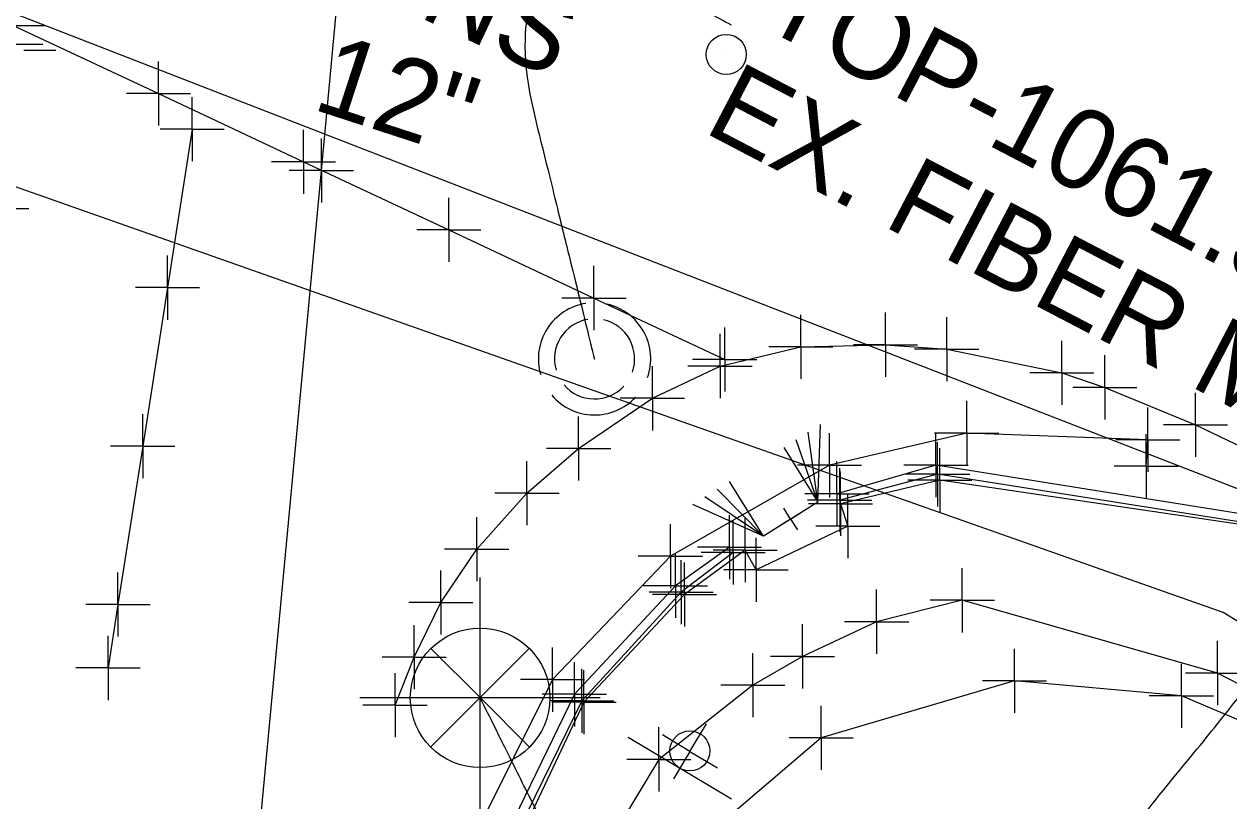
# Model space of a CAD drawing. Extents: x 0 to 1944463, y 0 to 420651.
# Drawn here: x 1942710.7 to 1942785.8, y 417761.8 to 417810.2 of the extents above; entities that cross this region are included whole.
import ezdxf

# ---------------------------------------------------------------- set-up
doc = ezdxf.new("R2010")
doc.units = 0
for name, color, linetype in [('AERIAL - CTRL - Points', 7, 'Continuous'), ('AERIAL - CTRL - Text', 7, 'Continuous'), ('SUR - DRG - Storm Sewer', 7, 'Continuous'), ('SUR - DRG - Storm Sewer Text', 7, 'Continuous'), ('SUR - DTM - Breaklines', 7, 'Continuous'), ('SUR - DTM - Breaklines - Points - Locators', 7, 'Continuous'), ('SUR - DTM - Spot Points - Locators', 7, 'Continuous'), ('SUR - PROPERTY - Property Lines', 7, 'Continuous'), ('SUR - TR-CTRL - Pavement Marking', 7, 'Continuous'), ('SUR - TR-CTRL - Pavement Marking - Points - Locators', 7, 'Continuous'), ('SUR - TR-CTRL - Signs and Devices', 7, 'Continuous'), ('SUR - TR-CTRL - Signs and Devices - Points - Locators', 7, 'Continuous'), ('SUR - TRAN - Features', 7, 'Continuous'), ('SUR - TRAN - Features - Points - Locators', 7, 'Continuous'), ('SUR - TRAN - Roads', 7, 'Continuous'), ('SUR - UTL - Fiber Optic Cable (Underground)', 7, 'Continuous'), ('SUR - UTL - Fiber Optic Cable (Underground) Text', 7, 'Continuous'), ('SUR - UTL - Water', 7, 'Continuous'), ('SUR - UTL - Water - Points - Locators', 7, 'Continuous')]:
    doc.layers.add(name, color=color, linetype=linetype)

msp = doc.modelspace()

# ---------------------------------------------------------------- linework, layer by layer
at = {"layer": 'AERIAL - CTRL - Points'}
for p, q in [((1942739.116, 417768.228), (1942739.116, 417775.728)), ((1942739.116, 417768.228), (1942736.047, 417771.297)), ((1942739.116, 417768.228), (1942742.184, 417771.297)), ((1942731.616, 417768.228), (1942739.116, 417768.228)), ((1942736.032, 417765.145), (1942739.116, 417768.228)), ((1942739.116, 417768.228), (1942739.116, 417768.228)), ((1942739.116, 417768.228), (1942746.615, 417768.228)), ((1942742.199, 417765.145), (1942739.116, 417768.228)), ((1942739.116, 417760.729), (1942739.116, 417768.228))]:
    msp.add_line(p, q, dxfattribs=at)
msp.add_circle((1942739.116, 417768.213), 4.35, dxfattribs=at)
at = {"layer": 'AERIAL - CTRL - Text'}
msp.add_open_spline([(1942778.809, 417721.49), (1942758.242, 417729.869), (1942739.116, 417768.228), (1942739.116, 417768.228)], degree=2, dxfattribs=at)
at = {"layer": 'SUR - DRG - Storm Sewer'}
msp.add_lwpolyline([(1942686.1, 417820.21), (1942792.82, 417778.75)], dxfattribs=at)
at = {"layer": 'SUR - DRG - Storm Sewer Text'}
msp.add_open_spline([(1942822.792, 417707.352), (1942764.259, 417740.655), (1942794.051, 417777.755), (1942794.051, 417777.755)], degree=2, dxfattribs=at)
at = {"layer": 'SUR - DTM - Breaklines'}
for points in [[(1942791.46, 417777.632), (1942789.584, 417778.697), (1942767.646, 417782.153), (1942761.543, 417780.542)], [(1942754.9, 417777.285), (1942751.657, 417774.809), (1942745.466, 417768.026), (1942741.083, 417759.074), (1942738.467, 417741.187), (1942737.586, 417732.685)], [(1942921.107, 417679.837), (1942919.961, 417678.775), (1942913.528, 417683.522), (1942876.22, 417712.505), (1942837.487, 417736.737), (1942800.473, 417757.298), (1942794.469, 417761.004), (1942792.318, 417764.328), (1942782.845, 417768.341), (1942772.445, 417769.28), (1942760.386, 417765.72), (1942751.56, 417758.18), (1942747.81, 417744.492), (1942745.106, 417731.919)]]:
    msp.add_lwpolyline(points, dxfattribs=at)
at = {"layer": 'SUR - DTM - Breaklines - Points - Locators'}
for p, q in [((1942767.646, 417782.153), (1942767.646, 417784.153)), ((1942761.543, 417780.542), (1942761.543, 417782.542)), ((1942767.646, 417782.153), (1942765.646, 417782.153)), ((1942767.646, 417782.153), (1942769.646, 417782.153)), ((1942767.646, 417782.153), (1942767.646, 417780.153)), ((1942761.543, 417780.542), (1942759.543, 417780.542)), ((1942761.543, 417780.542), (1942763.543, 417780.542)), ((1942761.543, 417780.542), (1942761.543, 417778.542)), ((1942754.9, 417777.285), (1942754.9, 417779.285)), ((1942754.9, 417777.285), (1942752.9, 417777.285)), ((1942754.9, 417777.285), (1942756.9, 417777.285)), ((1942754.9, 417777.285), (1942754.9, 417775.285)), ((1942751.657, 417774.809), (1942751.657, 417776.809)), ((1942751.657, 417774.809), (1942749.657, 417774.809)), ((1942751.657, 417774.809), (1942753.657, 417774.809)), ((1942751.657, 417774.809), (1942751.657, 417772.809)), ((1942772.445, 417769.28), (1942772.445, 417771.28)), ((1942745.466, 417768.026), (1942745.466, 417770.026)), ((1942782.845, 417768.341), (1942782.845, 417770.341)), ((1942772.445, 417769.28), (1942770.445, 417769.28)), ((1942772.445, 417769.28), (1942774.445, 417769.28)), ((1942772.445, 417769.28), (1942772.445, 417767.28)), ((1942782.845, 417768.341), (1942780.845, 417768.341)), ((1942782.845, 417768.341), (1942784.845, 417768.341)), ((1942782.845, 417768.341), (1942782.845, 417766.341)), ((1942745.466, 417768.026), (1942743.466, 417768.026)), ((1942745.466, 417768.026), (1942747.466, 417768.026)), ((1942745.466, 417768.026), (1942745.466, 417766.026)), ((1942760.386, 417765.72), (1942760.386, 417767.72)), ((1942760.386, 417765.72), (1942758.386, 417765.72)), ((1942760.386, 417765.72), (1942762.386, 417765.72)), ((1942760.386, 417765.72), (1942760.386, 417763.72))]:
    msp.add_line(p, q, dxfattribs=at)
at = {"layer": 'SUR - DTM - Spot Points - Locators'}
msp.add_line((1942754.48, 417808.32), (1942754.48, 417808.32), dxfattribs=at)
msp.add_circle((1942754.469, 417808.331), 1.25, dxfattribs=at)
at = {"layer": 'SUR - PROPERTY - Property Lines'}
for p, q in [((1942759.122, 417790.098), (1942759.122, 417792.098)), ((1942764.401, 417790.234), (1942764.401, 417792.234)), ((1942768.216, 417789.961), (1942768.216, 417791.961)), ((1942754.081, 417788.905), (1942754.081, 417790.905)), ((1942759.122, 417790.098), (1942757.122, 417790.098)), ((1942759.122, 417790.098), (1942761.122, 417790.098)), ((1942759.122, 417790.098), (1942759.122, 417788.098)), ((1942764.401, 417790.234), (1942762.401, 417790.234)), ((1942764.401, 417790.234), (1942766.401, 417790.234)), ((1942764.401, 417790.234), (1942764.401, 417788.234)), ((1942768.216, 417789.961), (1942766.216, 417789.961)), ((1942768.216, 417789.961), (1942770.216, 417789.961)), ((1942768.216, 417789.961), (1942768.216, 417787.961)), ((1942749.858, 417786.894), (1942749.858, 417788.894)), ((1942754.081, 417788.905), (1942752.081, 417788.905)), ((1942754.081, 417788.905), (1942756.081, 417788.905)), ((1942754.081, 417788.905), (1942754.081, 417786.905)), ((1942749.858, 417786.894), (1942747.858, 417786.894)), ((1942749.858, 417786.894), (1942751.858, 417786.894)), ((1942749.858, 417786.894), (1942749.858, 417784.894)), ((1942769.462, 417784.726), (1942769.462, 417786.726)), ((1942780.758, 417784.311), (1942780.758, 417786.311)), ((1942745.26, 417783.759), (1942745.26, 417785.759)), ((1942760.904, 417782.715), (1942760.904, 417784.715)), ((1942769.462, 417784.726), (1942767.462, 417784.726)), ((1942769.462, 417784.726), (1942771.462, 417784.726)), ((1942769.462, 417784.726), (1942769.462, 417782.726)), ((1942780.758, 417784.311), (1942778.758, 417784.311)), ((1942780.651, 417782.667), (1942780.651, 417784.667)), ((1942780.758, 417784.311), (1942782.758, 417784.311)), ((1942780.758, 417784.311), (1942780.758, 417782.311)), ((1942745.26, 417783.759), (1942743.26, 417783.759)), ((1942745.26, 417783.759), (1942747.26, 417783.759)), ((1942745.26, 417783.759), (1942745.26, 417781.759)), ((1942742.041, 417780.981), (1942742.041, 417782.981)), ((1942760.904, 417782.715), (1942758.904, 417782.715)), ((1942760.904, 417782.715), (1942762.904, 417782.715)), ((1942760.904, 417782.715), (1942760.904, 417780.715)), ((1942780.651, 417782.667), (1942778.651, 417782.667)), ((1942780.651, 417782.667), (1942782.651, 417782.667)), ((1942780.651, 417782.667), (1942780.651, 417780.667)), ((1942742.041, 417780.981), (1942740.041, 417780.981)), ((1942742.041, 417780.981), (1942744.041, 417780.981)), ((1942742.041, 417780.981), (1942742.041, 417778.981)), ((1942738.908, 417777.491), (1942738.908, 417779.491)), ((1942750.983, 417777.043), (1942750.983, 417779.043)), ((1942738.908, 417777.491), (1942736.908, 417777.491)), ((1942738.908, 417777.491), (1942740.908, 417777.491)), ((1942738.908, 417777.491), (1942738.908, 417775.491)), ((1942750.983, 417777.043), (1942748.983, 417777.043)), ((1942750.983, 417777.043), (1942752.983, 417777.043)), ((1942750.983, 417777.043), (1942750.983, 417775.043)), ((1942736.673, 417774.165), (1942736.673, 417776.165)), ((1942736.673, 417774.165), (1942734.673, 417774.165)), ((1942736.673, 417774.165), (1942738.673, 417774.165)), ((1942736.673, 417774.165), (1942736.673, 417772.165)), ((1942735.011, 417770.757), (1942735.011, 417772.757)), ((1942743.631, 417769.353), (1942743.631, 417771.353)), ((1942735.011, 417770.757), (1942733.011, 417770.757)), ((1942735.011, 417770.757), (1942737.011, 417770.757)), ((1942735.011, 417770.757), (1942735.011, 417768.757)), ((1942733.812, 417767.758), (1942733.812, 417769.758)), ((1942743.631, 417769.353), (1942741.631, 417769.353)), ((1942743.631, 417769.353), (1942745.631, 417769.353)), ((1942743.631, 417769.353), (1942743.631, 417767.353)), ((1942733.812, 417767.758), (1942731.812, 417767.758)), ((1942733.812, 417767.758), (1942735.812, 417767.758)), ((1942733.812, 417767.758), (1942733.812, 417765.758))]:
    msp.add_line(p, q, dxfattribs=at)
at = {"layer": 'SUR - TR-CTRL - Pavement Marking'}
for points in [[(1942710.007, 417810.141), (1942719.059, 417805.892), (1942728.111, 417801.642), (1942737.164, 417797.393), (1942746.216, 417793.144), (1942754.37, 417789.316)], [(1942721.166, 417803.674), (1942719.623, 417793.794), (1942718.079, 417783.914), (1942716.535, 417774.034), (1942715.917, 417770.08)], [(1942775.389, 417788.48), (1942778.077, 417787.573), (1942783.724, 417785.239), (1942789.24, 417782.599), (1942795.258, 417779.283), (1942803.951, 417774.34), (1942812.644, 417769.396), (1942821.336, 417764.453), (1942822.904, 417763.561), (1942831.499, 417758.45), (1942840.094, 417753.338), (1942848.689, 417748.226), (1942855.367, 417744.255), (1942863.768, 417738.83), (1942872.168, 417733.405), (1942877.884, 417729.714), (1942886.158, 417724.097), (1942893.929, 417718.822)]]:
    msp.add_lwpolyline(points, dxfattribs=at)
at = {"layer": 'SUR - TR-CTRL - Pavement Marking - Points - Locators'}
for p, q in [((1942710.007, 417810.141), (1942712.007, 417810.141)), ((1942709.862, 417808.967), (1942711.862, 417808.967)), ((1942710.665, 417808.592), (1942712.665, 417808.592)), ((1942719.059, 417805.892), (1942719.059, 417807.892)), ((1942719.059, 417805.892), (1942717.059, 417805.892)), ((1942719.059, 417805.892), (1942721.059, 417805.892)), ((1942719.059, 417805.892), (1942719.059, 417803.892)), ((1942721.166, 417803.674), (1942721.166, 417805.674)), ((1942721.166, 417803.674), (1942719.166, 417803.674)), ((1942721.166, 417803.674), (1942723.166, 417803.674)), ((1942721.166, 417803.674), (1942721.166, 417801.674)), ((1942728.111, 417801.642), (1942728.111, 417803.642)), ((1942728.111, 417801.642), (1942726.111, 417801.642)), ((1942728.111, 417801.642), (1942730.111, 417801.642)), ((1942728.111, 417801.642), (1942728.111, 417799.642)), ((1942737.164, 417797.393), (1942737.164, 417799.393)), ((1942708.971, 417798.737), (1942710.971, 417798.737)), ((1942737.164, 417797.393), (1942735.164, 417797.393)), ((1942737.164, 417797.393), (1942739.164, 417797.393)), ((1942737.164, 417797.393), (1942737.164, 417795.393)), ((1942719.623, 417793.794), (1942719.623, 417795.794)), ((1942746.216, 417793.144), (1942746.216, 417795.144)), ((1942719.623, 417793.794), (1942717.623, 417793.794)), ((1942719.623, 417793.794), (1942721.623, 417793.794)), ((1942719.623, 417793.794), (1942719.623, 417791.794)), ((1942746.216, 417793.144), (1942744.216, 417793.144)), ((1942746.216, 417793.144), (1942748.216, 417793.144)), ((1942746.216, 417793.144), (1942746.216, 417791.144)), ((1942754.37, 417789.316), (1942754.37, 417791.316)), ((1942775.389, 417788.48), (1942775.389, 417790.48)), ((1942775.389, 417788.48), (1942775.389, 417790.48)), ((1942754.37, 417789.316), (1942752.37, 417789.316)), ((1942754.37, 417789.316), (1942756.37, 417789.316)), ((1942754.37, 417789.316), (1942754.37, 417787.316)), ((1942778.077, 417787.573), (1942778.077, 417789.573)), ((1942775.389, 417788.48), (1942773.389, 417788.48)), ((1942775.389, 417788.48), (1942773.389, 417788.48)), ((1942775.389, 417788.48), (1942777.389, 417788.48)), ((1942775.389, 417788.48), (1942775.389, 417786.48)), ((1942775.389, 417788.48), (1942777.389, 417788.48)), ((1942775.389, 417788.48), (1942775.389, 417786.48)), ((1942778.077, 417787.573), (1942776.077, 417787.573)), ((1942778.077, 417787.573), (1942780.077, 417787.573)), ((1942778.077, 417787.573), (1942778.077, 417785.573)), ((1942783.724, 417785.239), (1942783.724, 417787.239)), ((1942718.079, 417783.914), (1942718.079, 417785.914)), ((1942783.724, 417785.239), (1942781.724, 417785.239)), ((1942783.724, 417785.239), (1942785.724, 417785.239)), ((1942783.724, 417785.239), (1942783.724, 417783.239)), ((1942718.079, 417783.914), (1942716.079, 417783.914)), ((1942718.079, 417783.914), (1942720.079, 417783.914)), ((1942718.079, 417783.914), (1942718.079, 417781.914)), ((1942716.535, 417774.034), (1942716.535, 417776.034)), ((1942716.535, 417774.034), (1942714.535, 417774.034)), ((1942716.535, 417774.034), (1942718.535, 417774.034)), ((1942716.535, 417774.034), (1942716.535, 417772.034)), ((1942715.917, 417770.08), (1942715.917, 417772.08)), ((1942715.917, 417770.08), (1942713.917, 417770.08)), ((1942715.917, 417770.08), (1942717.917, 417770.08)), ((1942715.917, 417770.08), (1942715.917, 417768.08))]:
    msp.add_line(p, q, dxfattribs=at)
at = {"layer": 'SUR - TR-CTRL - Signs and Devices'}
msp.add_line((1942754.79, 417761.897), (1942748.357, 417765.752), dxfattribs=at)
msp.add_circle((1942752.197, 417764.907), 1.25, dxfattribs=at)
at = {"layer": 'SUR - TR-CTRL - Signs and Devices - Points - Locators'}
for q in [(1942753.231, 417766.59), (1942750.487, 417765.902), (1942751.175, 417763.159), (1942753.918, 417763.846)]:
    msp.add_line((1942752.203, 417764.874), q, dxfattribs=at)
at = {"layer": 'SUR - TRAN - Features'}
for p, q in [((1942760.175, 417780.427), (1942760.344, 417785.25)), ((1942760.175, 417780.427), (1942758.818, 417784.296)), ((1942760.175, 417780.427), (1942759.581, 417784.773)), ((1942758.054, 417783.818), (1942760.175, 417780.427)), ((1942756.783, 417778.306), (1942753.899, 417781.221)), ((1942756.783, 417778.306), (1942754.662, 417781.698)), ((1942756.783, 417778.306), (1942753.136, 417780.744)), ((1942760.175, 417780.427), (1942756.783, 417778.306)), ((1942756.783, 417778.306), (1942752.373, 417780.267))]:
    msp.add_line(p, q, dxfattribs=at)
for points in [[(1942791.759, 417778.173), (1942789.79, 417779.172), (1942767.544, 417782.722), (1942761.369, 417780.945)], [(1942929.13, 417681.51), (1942884.161, 417715.389), (1942845.203, 417741.72), (1942802.72, 417767.087), (1942787.897, 417775.373), (1942789.188, 417778.635), (1942767.783, 417781.782), (1942761.592, 417780.32), (1942762.053, 417778.917), (1942756.325, 417776.202), (1942755.652, 417777.42), (1942751.861, 417774.655), (1942745.595, 417767.952), (1942741.365, 417759.013), (1942738.717, 417741.176), (1942737.876, 417732.681), (1942732.997, 417691.186), (1942729.793, 417661.663)], [(1942754.675, 417777.616), (1942751.296, 417775.206), (1942744.995, 417768.437), (1942740.544, 417759.233), (1942737.981, 417741.358), (1942737.175, 417732.556)], [(1943088.058, 417533.458), (1943083.95, 417537.719), (1943071.074, 417548.672), (1943056.792, 417560.53), (1943019.915, 417591.688), (1942990.429, 417618.512), (1942955.076, 417651.996), (1942925.728, 417676.871), (1942880.991, 417710.724), (1942841.949, 417736.86), (1942799.694, 417762.25), (1942785.094, 417769.761), (1942769.186, 417774.3), (1942763.842, 417772.965), (1942759.218, 417770.8), (1942756.13, 417769.011), (1942750.267, 417764.38), (1942746.064, 417757.407), (1942742.493, 417740.651), (1942741.733, 417732.524), (1942737.14, 417690.548), (1942733.569, 417661.203)]]:
    msp.add_lwpolyline(points, dxfattribs=at)
at = {"layer": 'SUR - TRAN - Features - Points - Locators'}
for p, q in [((1942767.544, 417782.722), (1942767.544, 417784.722)), ((1942767.783, 417781.782), (1942767.783, 417783.782)), ((1942761.369, 417780.945), (1942761.369, 417782.945)), ((1942767.544, 417782.722), (1942765.544, 417782.722)), ((1942767.544, 417782.722), (1942769.544, 417782.722)), ((1942767.544, 417782.722), (1942767.544, 417780.722)), ((1942761.592, 417780.32), (1942761.592, 417782.32)), ((1942767.783, 417781.782), (1942765.783, 417781.782)), ((1942767.783, 417781.782), (1942769.783, 417781.782)), ((1942767.783, 417781.782), (1942767.783, 417779.782)), ((1942761.369, 417780.945), (1942759.369, 417780.945)), ((1942761.592, 417780.32), (1942759.592, 417780.32)), ((1942761.369, 417780.945), (1942763.369, 417780.945)), ((1942761.369, 417780.945), (1942761.369, 417778.945)), ((1942761.592, 417780.32), (1942763.592, 417780.32)), ((1942761.592, 417780.32), (1942761.592, 417778.32)), ((1942762.053, 417778.917), (1942762.053, 417780.917)), ((1942754.675, 417777.616), (1942754.675, 417779.616)), ((1942758.479, 417779.366), (1942758.055, 417780.045)), ((1942758.479, 417779.366), (1942759.157, 417779.79)), ((1942755.652, 417777.42), (1942755.652, 417779.42)), ((1942758.479, 417779.366), (1942757.8, 417778.942)), ((1942758.479, 417779.366), (1942758.903, 417778.688)), ((1942762.053, 417778.917), (1942760.053, 417778.917)), ((1942762.053, 417778.917), (1942764.053, 417778.917)), ((1942762.053, 417778.917), (1942762.053, 417776.917)), ((1942756.325, 417776.202), (1942756.325, 417778.202)), ((1942754.675, 417777.616), (1942752.675, 417777.616)), ((1942755.652, 417777.42), (1942753.652, 417777.42)), ((1942754.675, 417777.616), (1942756.675, 417777.616)), ((1942754.675, 417777.616), (1942754.675, 417775.616)), ((1942755.652, 417777.42), (1942757.652, 417777.42)), ((1942755.652, 417777.42), (1942755.652, 417775.42)), ((1942751.296, 417775.206), (1942751.296, 417777.206)), ((1942751.861, 417774.655), (1942751.861, 417776.655)), ((1942756.325, 417776.202), (1942754.325, 417776.202)), ((1942756.325, 417776.202), (1942758.325, 417776.202)), ((1942756.325, 417776.202), (1942756.325, 417774.202)), ((1942769.186, 417774.3), (1942769.186, 417776.3)), ((1942751.296, 417775.206), (1942749.296, 417775.206)), ((1942751.296, 417775.206), (1942753.296, 417775.206)), ((1942751.296, 417775.206), (1942751.296, 417773.206)), ((1942751.861, 417774.655), (1942749.861, 417774.655)), ((1942751.861, 417774.655), (1942753.861, 417774.655)), ((1942751.861, 417774.655), (1942751.861, 417772.655)), ((1942763.842, 417772.965), (1942763.842, 417774.965)), ((1942769.186, 417774.3), (1942767.186, 417774.3)), ((1942769.186, 417774.3), (1942771.186, 417774.3)), ((1942769.186, 417774.3), (1942769.186, 417772.3)), ((1942759.218, 417770.8), (1942759.218, 417772.8)), ((1942763.842, 417772.965), (1942761.842, 417772.965)), ((1942763.842, 417772.965), (1942765.842, 417772.965)), ((1942763.842, 417772.965), (1942763.842, 417770.965)), ((1942785.094, 417769.761), (1942785.094, 417771.761)), ((1942756.13, 417769.011), (1942756.13, 417771.011)), ((1942759.218, 417770.8), (1942757.218, 417770.8)), ((1942759.218, 417770.8), (1942761.218, 417770.8)), ((1942759.218, 417770.8), (1942759.218, 417768.8)), ((1942744.995, 417768.437), (1942744.995, 417770.437)), ((1942745.595, 417767.952), (1942745.595, 417769.952)), ((1942785.094, 417769.761), (1942783.094, 417769.761)), ((1942785.094, 417769.761), (1942787.094, 417769.761)), ((1942785.094, 417769.761), (1942785.094, 417767.761)), ((1942756.13, 417769.011), (1942754.13, 417769.011)), ((1942756.13, 417769.011), (1942758.13, 417769.011)), ((1942756.13, 417769.011), (1942756.13, 417767.011)), ((1942744.995, 417768.437), (1942742.995, 417768.437)), ((1942744.995, 417768.437), (1942746.995, 417768.437)), ((1942744.995, 417768.437), (1942744.995, 417766.437)), ((1942745.595, 417767.952), (1942743.595, 417767.952)), ((1942745.595, 417767.952), (1942747.595, 417767.952)), ((1942745.595, 417767.952), (1942745.595, 417765.952)), ((1942750.267, 417764.38), (1942750.267, 417766.38)), ((1942750.267, 417764.38), (1942748.267, 417764.38)), ((1942750.267, 417764.38), (1942752.267, 417764.38)), ((1942750.267, 417764.38), (1942750.267, 417762.38))]:
    msp.add_line(p, q, dxfattribs=at)
at = {"layer": 'SUR - TRAN - Roads'}
msp.add_line((1942768.216, 417789.961), (1942775.389, 417788.48), dxfattribs=at)
for points in [[(1942733.812, 417767.758), (1942735.011, 417770.757), (1942736.673, 417774.165), (1942738.908, 417777.491), (1942742.041, 417780.981), (1942745.26, 417783.759), (1942749.858, 417786.894), (1942754.081, 417788.905), (1942759.122, 417790.098), (1942764.401, 417790.234), (1942768.216, 417789.961)], [(1942780.651, 417782.667), (1942780.758, 417784.311), (1942769.462, 417784.726), (1942760.904, 417782.715), (1942750.983, 417777.043), (1942743.631, 417769.353), (1942738.82, 417759.684), (1942736.226, 417741.63), (1942735.149, 417732.33)]]:
    msp.add_lwpolyline(points, dxfattribs=at)
at = {"layer": 'SUR - UTL - Fiber Optic Cable (Underground)'}
msp.add_lwpolyline([(1943675.935, 416874.811), (1943301.532, 417291.453), (1943229.017, 417377.593), (1943204.769, 417412.08), (1943079.474, 417545.559), (1943001.447, 417611.824), (1942943.851, 417666.04), (1942875.969, 417717.873), (1942785.445, 417773.544), (1942671.047, 417813.855), (1942647.996, 417834.422), (1942364.461, 417940.541)], dxfattribs=at)
for radius, start, end in [(3.5, 98.95945, 196.2542), (3.5, 340.55316, 76.99944), (2.5, 99.76186, 196.20006), (2.5, 340.55043, 77.09543), (3.5, 220.39621, 317.18929), (2.5, 220.31418, 317.14876)]:
    msp.add_arc((1942746.256, 417789.351), radius, start, end, dxfattribs=at)
at = {"layer": 'SUR - UTL - Fiber Optic Cable (Underground) Text'}
msp.add_open_spline([(1942754.786, 417810.158), (1942738.92, 417819.125), (1942746.242, 417789.355), (1942746.242, 417789.355)], degree=2, dxfattribs=at)
at = {"layer": 'SUR - UTL - Water'}
msp.add_lwpolyline([(1942721.71, 417720.78), (1942729.22, 417801.1), (1942737.09, 417885.44), (1942743.84, 417957.42), (1942750.2, 418026.1), (1942756.89, 418096.95)], dxfattribs=at)
at = {"layer": 'SUR - UTL - Water - Points - Locators'}
for q in [(1942729.22, 417803.1), (1942729.22, 417803.1), (1942727.22, 417801.1), (1942727.22, 417801.1), (1942731.22, 417801.1), (1942729.22, 417799.1), (1942731.22, 417801.1), (1942729.22, 417799.1)]:
    msp.add_line((1942729.22, 417801.1), q, dxfattribs=at)

# ---------------------------------------------------------------- texts
at = {"layer": 'SUR - DRG - Storm Sewer Text'}
for s, height, rotation, p in [(' CONST. PLANS', 4.99999, 334.95226, (1942697.491, 417828.334)), ('12"', 5, 341.9454, (1942728.56, 417804.957))]:
    msp.add_text(s, height=height, rotation=rotation, dxfattribs=at).set_placement(p)
at = {"layer": 'SUR - UTL - Fiber Optic Cable (Underground) Text'}
for s, p in [("TOP-1061.30'", (1942756.427, 417810.187)), ('EX. FIBER MH', (1942752.955, 417803.54))]:
    msp.add_text(s, height=4.99999, rotation=332.42224, dxfattribs=at).set_placement(p)

doc.saveas('drawing.dxf')
